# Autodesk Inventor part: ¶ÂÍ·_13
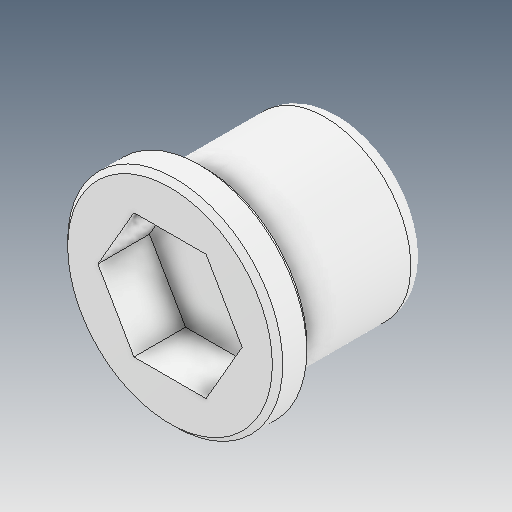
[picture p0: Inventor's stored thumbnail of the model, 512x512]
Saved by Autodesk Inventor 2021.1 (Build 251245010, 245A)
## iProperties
Created: 2021-06
Part Number: ¶ÂÍ·_13
Material: Ogólny
Document SubType Name: Modeling
Designer: user
Density: 1 g/cm^3
Appearance: Domyślna
Author: user
Revision Number: ÈÎºÎ
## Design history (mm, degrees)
feature "ÊäÈë1"
node "Bryła1"
